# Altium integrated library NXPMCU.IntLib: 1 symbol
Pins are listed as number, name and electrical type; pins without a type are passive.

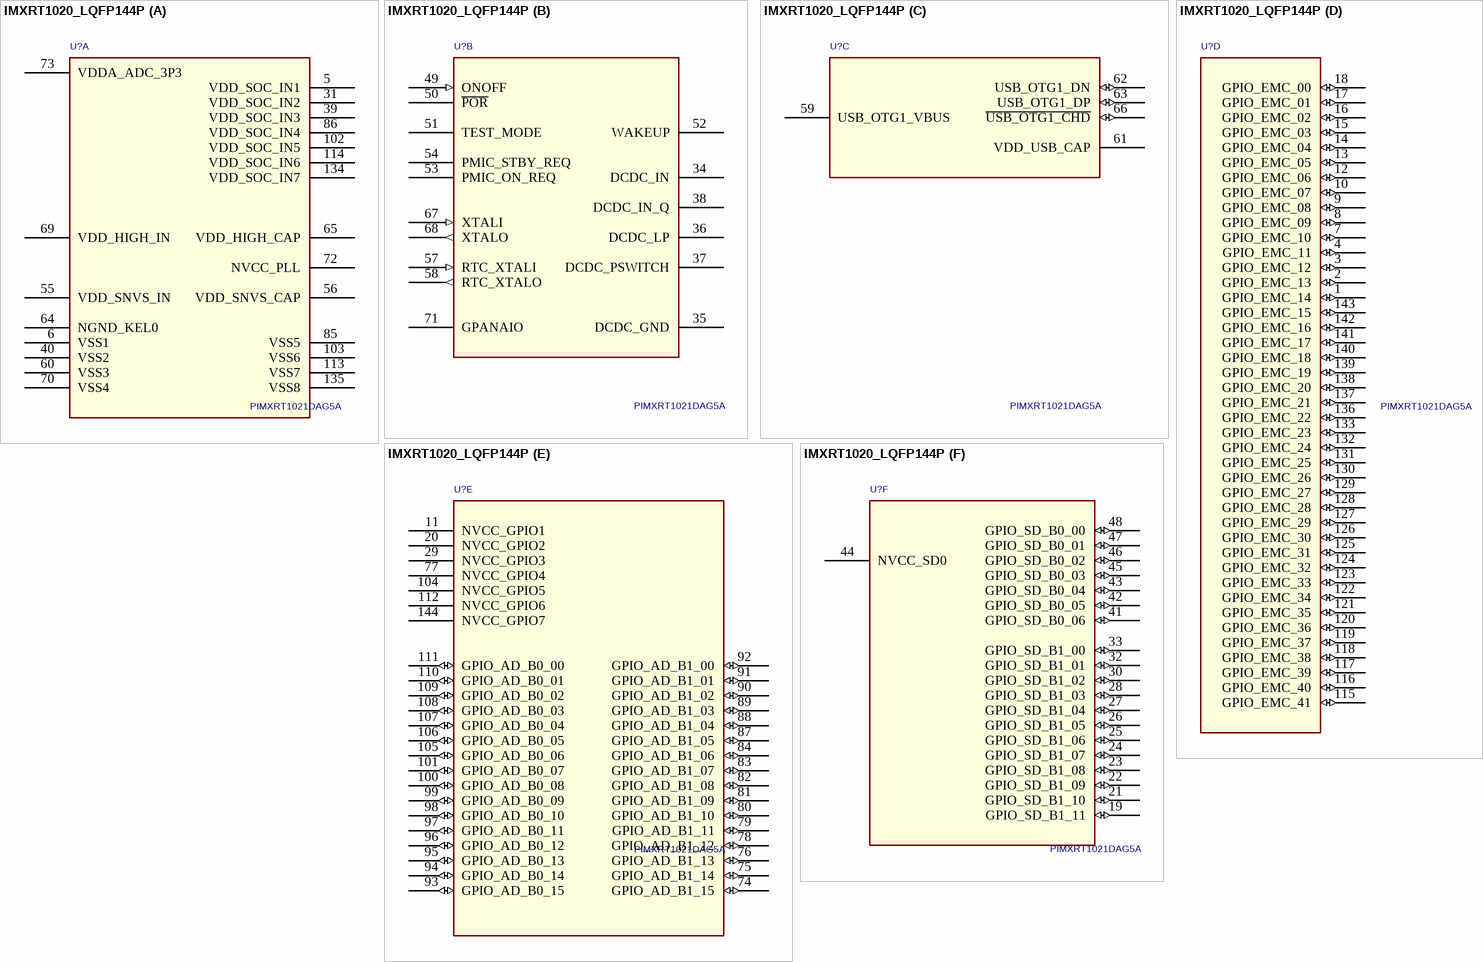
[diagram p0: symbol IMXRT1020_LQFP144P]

## IMXRT1020_LQFP144P
designator U?, comment PIMXRT1021DAG5A
IC CPU ARM Cortex-M7 500MHZ 1.3V LQFP144; SWAP_INFO: (S1+S2+S3+S4+S5+S6); SPLIT_INST: TRUE; AGILE_PN: TMP-WF-30803; MFG_NAME01: NXP SEMICONDUCTORS; MFG_PN01: I.MXRT1020; PRE_APN: 330-77054; CAD_APPROVED: Yes
footprint LQFP50P2200X2200X160-144N (TSQFP, 144-Leads, Body 20.00x20.00mm, Pitch 0.50mm, IPC Medium Density)
part A pins: 5 VDD_SOC_IN1 (power), 6 VSS1 (power), 31 VDD_SOC_IN2 (power), 39 VDD_SOC_IN3 (power), 40 VSS2 (power), 55 VDD_SNVS_IN (power), 56 VDD_SNVS_CAP (power), 60 VSS3 (power), 64 NGND_KEL0 (power), 65 VDD_HIGH_CAP (power), 69 VDD_HIGH_IN (power), 70 VSS4 (power), 72 NVCC_PLL (power), 73 VDDA_ADC_3P3 (power), 85 VSS5 (power), 86 VDD_SOC_IN4 (power), 102 VDD_SOC_IN5 (power), 103 VSS6 (power), 113 VSS7 (power), 114 VDD_SOC_IN6 (power), 134 VDD_SOC_IN7 (power), 135 VSS8 (power)
part B pins: 34 DCDC_IN, 35 DCDC_GND (power), 36 DCDC_LP (power), 37 DCDC_PSWITCH, 38 DCDC_IN_Q, 49 ONOFF (in), 50 ~{POR}, 51 TEST_MODE, 52 WAKEUP, 53 PMIC_ON_REQ, 54 PMIC_STBY_REQ, 57 RTC_XTALI (in), 58 RTC_XTALO (out), 67 XTALI (in), 68 XTALO (out), 71 GPANAIO (power)
part C pins: 59 USB_OTG1_VBUS (power), 61 VDD_USB_CAP (power), 62 USB_OTG1_DN (io), 63 USB_OTG1_DP (io), 66 ~{USB_OTG1_CHD} (io)
part D pins: 1 GPIO_EMC_14 (io), 2 GPIO_EMC_13 (io), 3 GPIO_EMC_12 (io), 4 GPIO_EMC_11 (io), 7 GPIO_EMC_10 (io), 8 GPIO_EMC_09 (io), 9 GPIO_EMC_08 (io), 10 GPIO_EMC_07 (io), 12 GPIO_EMC_06 (io), 13 GPIO_EMC_05 (io), 14 GPIO_EMC_04 (io), 15 GPIO_EMC_03 (io), 16 GPIO_EMC_02 (io), 17 GPIO_EMC_01 (io), 18 GPIO_EMC_00 (io), 115 GPIO_EMC_41 (io), 116 GPIO_EMC_40 (io), 117 GPIO_EMC_39 (io), 118 GPIO_EMC_38 (io), 119 GPIO_EMC_37 (io), 120 GPIO_EMC_36 (io), 121 GPIO_EMC_35 (io), 122 GPIO_EMC_34 (io), 123 GPIO_EMC_33 (io), 124 GPIO_EMC_32 (io), 125 GPIO_EMC_31 (io), 126 GPIO_EMC_30 (io), 127 GPIO_EMC_29 (io), 128 GPIO_EMC_28 (io), 129 GPIO_EMC_27 (io), 130 GPIO_EMC_26 (io), 131 GPIO_EMC_25 (io), 132 GPIO_EMC_24 (io), 133 GPIO_EMC_23 (io), 136 GPIO_EMC_22 (io), 137 GPIO_EMC_21 (io), 138 GPIO_EMC_20 (io), 139 GPIO_EMC_19 (io), 140 GPIO_EMC_18 (io), 141 GPIO_EMC_17 (io), 142 GPIO_EMC_16 (io), 143 GPIO_EMC_15 (io)
part E pins: 11 NVCC_GPIO1 (power), 20 NVCC_GPIO2 (power), 29 NVCC_GPIO3 (power), 74 GPIO_AD_B1_15 (io), 75 GPIO_AD_B1_14 (io), 76 GPIO_AD_B1_13 (io), 77 NVCC_GPIO4 (power), 78 GPIO_AD_B1_12 (io), 79 GPIO_AD_B1_11 (io), 80 GPIO_AD_B1_10 (io), 81 GPIO_AD_B1_09 (io), 82 GPIO_AD_B1_08 (io), 83 GPIO_AD_B1_07 (io), 84 GPIO_AD_B1_06 (io), 87 GPIO_AD_B1_05 (io), 88 GPIO_AD_B1_04 (io), 89 GPIO_AD_B1_03 (io), 90 GPIO_AD_B1_02 (io), 91 GPIO_AD_B1_01 (io), 92 GPIO_AD_B1_00 (io), 93 GPIO_AD_B0_15 (io), 94 GPIO_AD_B0_14 (io), 95 GPIO_AD_B0_13 (io), 96 GPIO_AD_B0_12 (io), 97 GPIO_AD_B0_11 (io), 98 GPIO_AD_B0_10 (io), 99 GPIO_AD_B0_09 (io), 100 GPIO_AD_B0_08 (io), 101 GPIO_AD_B0_07 (io), 104 NVCC_GPIO5 (power), 105 GPIO_AD_B0_06 (io), 106 GPIO_AD_B0_05 (io), 107 GPIO_AD_B0_04 (io), 108 GPIO_AD_B0_03 (io), 109 GPIO_AD_B0_02 (io), 110 GPIO_AD_B0_01 (io), 111 GPIO_AD_B0_00 (io), 112 NVCC_GPIO6 (power), 144 NVCC_GPIO7 (power)
part F pins: 19 GPIO_SD_B1_11 (io), 21 GPIO_SD_B1_10 (io), 22 GPIO_SD_B1_09 (io), 23 GPIO_SD_B1_08 (io), 24 GPIO_SD_B1_07 (io), 25 GPIO_SD_B1_06 (io), 26 GPIO_SD_B1_05 (io), 27 GPIO_SD_B1_04 (io), 28 GPIO_SD_B1_03 (io), 30 GPIO_SD_B1_02 (io), 32 GPIO_SD_B1_01 (io), 33 GPIO_SD_B1_00 (io), 41 GPIO_SD_B0_06 (io), 42 GPIO_SD_B0_05 (io), 43 GPIO_SD_B0_04 (io), 44 NVCC_SD0 (power), 45 GPIO_SD_B0_03 (io), 46 GPIO_SD_B0_02 (io), 47 GPIO_SD_B0_01 (io), 48 GPIO_SD_B0_00 (io)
